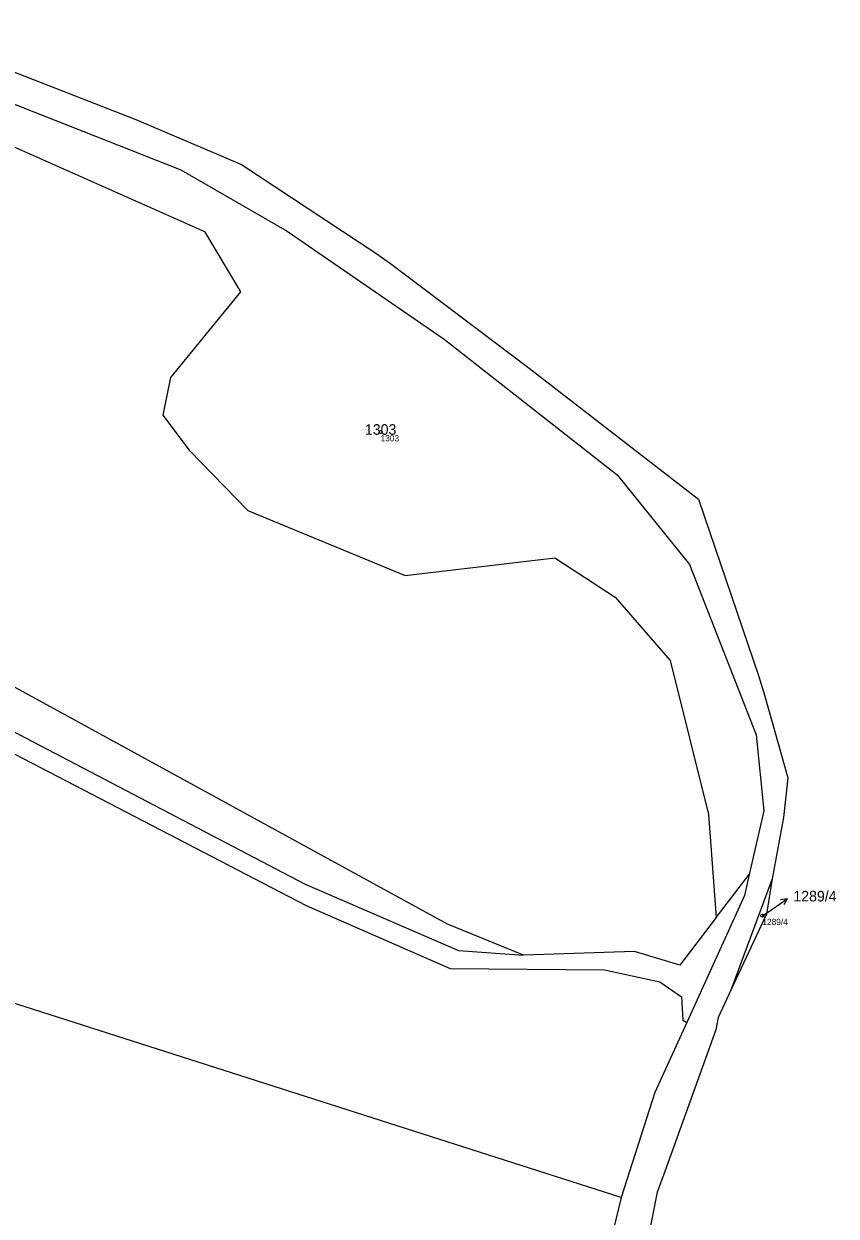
# Model space of a CAD drawing. Extents: x -869390 to -864576, y -1040967 to -1036941.
# Drawn here: x -868372 to -868241.4, y -1039384.4 to -1039192.7 of the extents above; entities that cross this region are included whole.
import ezdxf

# ---------------------------------------------------------------- set-up
doc = ezdxf.new("R2010")
doc.units = 0
for name, color, linetype in [('Definiční body', 7, 'Continuous'), ('Hranice parcel', 7, 'Continuous'), ('Parcelní čísla', 7, 'Continuous'), ('Pop  PČ popisy', 7, 'Continuous')]:
    doc.layers.add(name, color=color, linetype=linetype)

msp = doc.modelspace()

# ---------------------------------------------------------------- linework, layer by layer
at = {"layer": 'Definiční body'}
for centre in [(-868314.61, -1039258.33), (-868253.22, -1039336.07)]:
    msp.add_circle(centre, 0.25, dxfattribs=at)
at = {"layer": 'Hranice parcel'}
for p, q in [((-868393.27, -1039192.71), (-868353.98, -1039208.1)), ((-868399.05, -1039195.55), (-868346.75, -1039216.2)), ((-868400.62, -1039200.46), (-868342.94, -1039226.07)), ((-868353.98, -1039208.1), (-868336.96, -1039215.31)), ((-868346.75, -1039216.2), (-868329.63, -1039226.05)), ((-868336.96, -1039215.31), (-868315.4, -1039229.57)), ((-868342.94, -1039226.07), (-868337.16, -1039235.76)), ((-868329.63, -1039226.05), (-868304.36, -1039243.42)), ((-868315.4, -1039229.57), (-868312.99, -1039231.23)), ((-868312.99, -1039231.23), (-868290.73, -1039248.08)), ((-868337.16, -1039235.76), (-868348.38, -1039249.56)), ((-868304.36, -1039243.42), (-868276.55, -1039265.18)), ((-868348.38, -1039249.56), (-868349.65, -1039255.61)), ((-868290.73, -1039248.08), (-868263.51, -1039269.12)), ((-868349.65, -1039255.61), (-868345.37, -1039261.23)), ((-868345.37, -1039261.23), (-868335.95, -1039270.92)), ((-868276.55, -1039265.18), (-868264.95, -1039279.62)), ((-868263.51, -1039269.12), (-868253.79, -1039297.63)), ((-868335.95, -1039270.92), (-868310.66, -1039281.4)), ((-868310.66, -1039281.4), (-868286.59, -1039278.52)), ((-868286.59, -1039278.52), (-868276.87, -1039284.84)), ((-868264.95, -1039279.62), (-868254.22, -1039306.97)), ((-868412.94, -1039285.93), (-868326.82, -1039330.96)), ((-868276.87, -1039284.84), (-868268.04, -1039295.02)), ((-868303.87, -1039337.44), (-868389.7, -1039290.47)), ((-868406.04, -1039293.17), (-868326.6, -1039334.41)), ((-868268.04, -1039295.02), (-868261.9, -1039319.79)), ((-868253.79, -1039297.63), (-868252.81, -1039300.75)), ((-868252.81, -1039300.75), (-868249.14, -1039313.92)), ((-868254.22, -1039306.97), (-868252.98, -1039319.19)), ((-868249.14, -1039313.92), (-868249.81, -1039320.3)), ((-868261.9, -1039319.79), (-868260.67, -1039336.36)), ((-868252.98, -1039319.19), (-868255.32, -1039329.44)), ((-868249.81, -1039320.3), (-868251.67, -1039330.13)), ((-868260.67, -1039336.36), (-868255.32, -1039329.44)), ((-868251.67, -1039330.13), (-868258.3, -1039348.05)), ((-868255.32, -1039329.44), (-868256.09, -1039332.79)), ((-868251.67, -1039330.13), (-868252.53, -1039335.8)), ((-868326.82, -1039330.96), (-868302.09, -1039341.65)), ((-868256.09, -1039332.79), (-868265.38, -1039353.24)), ((-868326.6, -1039334.41), (-868303.4, -1039344.54)), ((-868252.53, -1039335.8), (-868258.3, -1039348.05)), ((-868291.61, -1039342.39), (-868303.87, -1039337.44)), ((-868260.67, -1039336.36), (-868266.47, -1039343.99)), ((-868302.09, -1039341.65), (-868291.61, -1039342.39)), ((-868273.8, -1039341.81), (-868291.61, -1039342.39)), ((-868266.47, -1039343.99), (-868273.8, -1039341.81)), ((-868303.4, -1039344.54), (-868278.63, -1039344.75)), ((-868278.63, -1039344.75), (-868269.73, -1039346.68)), ((-868269.73, -1039346.68), (-868266.25, -1039349.1)), ((-868266.25, -1039349.1), (-868266, -1039352.88)), ((-868258.3, -1039348.05), (-868260.33, -1039352.41)), ((-868275.9, -1039381.38), (-868375.82, -1039349.4)), ((-868266, -1039352.88), (-868265.38, -1039353.24)), ((-868260.33, -1039352.41), (-868260.68, -1039354.42)), ((-868265.38, -1039353.24), (-868270.49, -1039364.49)), ((-868260.68, -1039354.42), (-868268.92, -1039377.16)), ((-868270.49, -1039364.49), (-868275.9, -1039381.38)), ((-868268.92, -1039377.16), (-868270.11, -1039380.48)), ((-868275.9, -1039381.38), (-868278.1, -1039390.19)), ((-868270.11, -1039380.48), (-868272.49, -1039392.5))]:
    msp.add_line(p, q, dxfattribs=at)
at = {"layer": 'Pop  PČ popisy'}
for p, q in [((-868251.71, -1039335.04), (-868249.22, -1039333.36)), ((-868249.22, -1039333.36), (-868250.33, -1039333.51)), ((-868249.22, -1039333.36), (-868249.77, -1039334.34)), ((-868253.22, -1039336.07), (-868251.71, -1039335.04))]:
    msp.add_line(p, q, dxfattribs=at)

# ---------------------------------------------------------------- texts
at = {"layer": 'Definiční body'}
for s, p in [('1303', (-868314.61, -1039259.82)), ('1289/4', (-868253.22, -1039337.56))]:
    msp.add_text(s, height=1, dxfattribs=at).set_placement(p)
at = {"layer": 'Parcelní čísla'}
for s, p in [('1303', (-868317.13, -1039258.76)), ('1289/4', (-868248.24, -1039333.77))]:
    msp.add_text(s, height=1.7, dxfattribs=at).set_placement(p)

doc.saveas('drawing.dxf')
